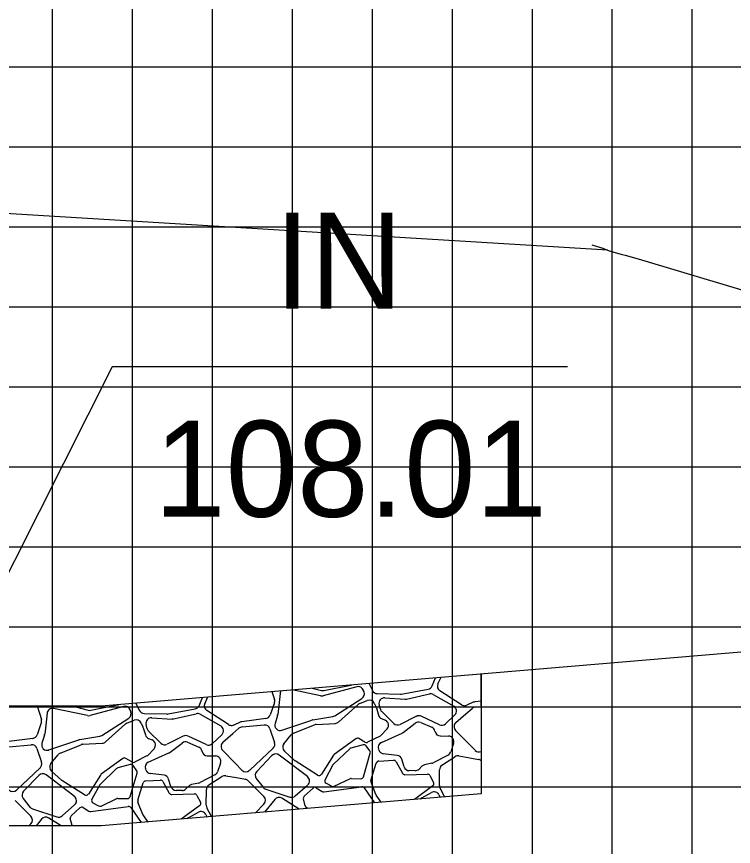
# Model space of a CAD drawing. Extents: x 1685192 to 1685536, y 461260 to 461480.
# Drawn here: x 1685380.78 to 1685389.74, y 461431.46 to 461441.84 of the extents above; entities that cross this region are included whole.
import ezdxf

# ---------------------------------------------------------------- set-up
doc = ezdxf.new("R2010")
doc.units = 0
for name, color, linetype in [('ANNOTATION', 7, 'Continuous'), ('D_Roadway_Centerline', 7, 'Continuous'), ('D_Roadway_SlopeLines', 7, 'Continuous'), ('MAJOR', 7, 'Continuous'), ('MINOR', 7, 'Continuous'), ('S_Roadway_Centerline', 7, 'Continuous')]:
    doc.layers.add(name, color=color, linetype=linetype)

msp = doc.modelspace()

# ---------------------------------------------------------------- linework, layer by layer
at = {"layer": 'ANNOTATION'}
msp.add_lwpolyline([(1685387.668, 461437.456), (1685381.977, 461437.456), (1685379.839, 461433.216)], dxfattribs=at)
at = {"layer": 'D_Roadway_Centerline'}
for p, q in [((1685385.186, 461433.5), (1685385.229, 461433.41)), ((1685385.977, 461433.468), (1685386.019, 461433.57)), ((1685386.049, 461433.492), (1685386.088, 461433.576)), ((1685383.974, 461433.397), (1685384.005, 461433.296)), ((1685384.582, 461433.343), (1685384.226, 461433.418)), ((1685384.477, 461433.439), (1685384.592, 461433.41)), ((1685385.035, 461433.457), (1685384.614, 461433.344)), ((1685384.622, 461433.41), (1685384.958, 461433.477)), ((1685385.125, 461433.392), (1685385.116, 461433.415)), ((1685385.589, 461433.364), (1685385.926, 461433.426)), ((1685386.345, 461433.23), (1685386.073, 461433.406)), ((1685383.063, 461433.22), (1685383.104, 461433.323)), ((1685383.134, 461433.245), (1685383.174, 461433.329)), ((1685384.076, 461433.373), (1685384.046, 461433.11)), ((1685384.76, 461433.095), (1685385.097, 461433.311)), ((1685385.072, 461433.247), (1685385.165, 461433.285)), ((1685385.289, 461433.371), (1685385.575, 461433.363)), ((1685385.385, 461433.317), (1685385.638, 461433.301)), ((1685385.657, 461433.302), (1685385.942, 461433.367)), ((1685385.991, 461433.36), (1685386.247, 461433.214)), ((1685386.589, 461433.278), (1685386.51, 461433.268)), ((1685381.039, 461433.216), (1685381.091, 461433.049)), ((1685381.668, 461433.096), (1685381.244, 461433.185)), ((1685381.47, 461433.216), (1685381.677, 461433.163)), ((1685382.12, 461433.21), (1685381.699, 461433.097)), ((1685381.708, 461433.162), (1685382.043, 461433.23)), ((1685382.272, 461433.252), (1685382.315, 461433.162)), ((1685382.675, 461433.117), (1685383.012, 461433.179)), ((1685384.004, 461433.254), (1685383.953, 461433.104)), ((1685384.808, 461433.016), (1685385.052, 461433.235)), ((1685385.253, 461433.25), (1685385.275, 461433.201)), ((1685385.279, 461433.192), (1685385.305, 461433.102)), ((1685385.329, 461433.178), (1685385.314, 461433.231)), ((1685386.399, 461433.119), (1685386.475, 461433.185)), ((1685386.491, 461433.262), (1685386.41, 461433.226)), ((1685386.514, 461433.202), (1685386.589, 461433.208)), ((1685381.162, 461433.126), (1685381.132, 461432.863)), ((1685382.21, 461433.145), (1685382.202, 461433.167)), ((1685382.375, 461433.124), (1685382.66, 461433.116)), ((1685382.471, 461433.069), (1685382.724, 461433.053)), ((1685382.743, 461433.055), (1685383.028, 461433.12)), ((1685383.077, 461433.112), (1685383.333, 461432.966)), ((1685383.431, 461432.983), (1685383.159, 461433.158)), ((1685384.043, 461433.097), (1685384.012, 461432.999)), ((1685384.484, 461433.043), (1685384.734, 461433.085)), ((1685385.498, 461432.998), (1685385.347, 461433.147)), ((1685385.779, 461433.087), (1685385.576, 461432.986)), ((1685386.067, 461432.98), (1685385.839, 461433.087)), ((1685386.26, 461433.105), (1685386.143, 461432.993)), ((1685386.274, 461433.01), (1685386.399, 461433.119)), ((1685381.09, 461433.006), (1685381.038, 461432.857)), ((1685381.846, 461432.847), (1685382.183, 461433.064)), ((1685381.893, 461432.768), (1685382.138, 461432.987)), ((1685382.158, 461433), (1685382.251, 461433.038)), ((1685382.339, 461433.003), (1685382.361, 461432.954)), ((1685382.415, 461432.93), (1685382.4, 461432.983)), ((1685383.577, 461433.015), (1685383.496, 461432.978)), ((1685383.897, 461433.059), (1685383.596, 461433.02)), ((1685383.6, 461432.955), (1685383.878, 461432.979)), ((1685384.099, 461432.913), (1685384.474, 461433.04)), ((1685384.241, 461432.875), (1685384.504, 461432.98)), ((1685384.525, 461432.985), (1685384.766, 461432.998)), ((1685385.345, 461433.058), (1685385.39, 461433.039)), ((1685385.614, 461432.884), (1685385.765, 461433)), ((1685385.833, 461433.009), (1685385.972, 461432.95)), ((1685382.365, 461432.945), (1685382.391, 461432.855)), ((1685382.583, 461432.751), (1685382.433, 461432.899)), ((1685383.36, 461432.763), (1685383.485, 461432.872)), ((1685383.485, 461432.872), (1685383.561, 461432.938)), ((1685383.949, 461432.932), (1685384.007, 461432.759)), ((1685385.413, 461432.93), (1685385.335, 461432.846)), ((1685385.342, 461432.76), (1685385.6, 461432.876)), ((1685386.012, 461432.901), (1685386.013, 461432.896)), ((1685386.431, 461432.746), (1685386.27, 461432.911)), ((1685380.982, 461432.811), (1685380.682, 461432.773)), ((1685381.129, 461432.85), (1685381.098, 461432.751)), ((1685381.185, 461432.666), (1685381.56, 461432.793)), ((1685381.57, 461432.795), (1685381.82, 461432.838)), ((1685382.43, 461432.811), (1685382.475, 461432.792)), ((1685382.865, 461432.839), (1685382.662, 461432.738)), ((1685382.919, 461432.762), (1685383.058, 461432.703)), ((1685383.152, 461432.733), (1685382.925, 461432.84)), ((1685383.346, 461432.857), (1685383.229, 461432.745)), ((1685384.124, 461432.743), (1685384.213, 461432.854)), ((1685385.022, 461432.807), (1685384.753, 461432.609)), ((1685385.136, 461432.763), (1685385.06, 461432.808)), ((1685385.325, 461432.838), (1685385.169, 461432.762)), ((1685386.079, 461432.842), (1685386.181, 461432.84)), ((1685380.686, 461432.707), (1685380.964, 461432.731)), ((1685381.035, 461432.685), (1685381.092, 461432.512)), ((1685381.327, 461432.628), (1685381.59, 461432.732)), ((1685381.611, 461432.737), (1685381.852, 461432.751)), ((1685382.499, 461432.682), (1685382.42, 461432.598)), ((1685382.7, 461432.637), (1685382.851, 461432.753)), ((1685383.517, 461432.499), (1685383.356, 461432.663)), ((1685383.988, 461432.688), (1685383.695, 461432.412)), ((1685384.947, 461432.681), (1685384.743, 461432.487)), ((1685385.115, 461432.731), (1685384.961, 461432.69)), ((1685385.197, 461432.654), (1685385.152, 461432.718)), ((1685385.309, 461432.666), (1685385.305, 461432.676)), ((1685386.245, 461432.749), (1685386.208, 461432.641)), ((1685386.514, 461432.662), (1685386.431, 461432.746)), ((1685381.21, 461432.496), (1685381.299, 461432.607)), ((1685382.108, 461432.559), (1685381.838, 461432.362)), ((1685382.222, 461432.516), (1685382.145, 461432.561)), ((1685382.41, 461432.591), (1685382.254, 461432.514)), ((1685382.428, 461432.513), (1685382.686, 461432.629)), ((1685383.098, 461432.654), (1685383.099, 461432.649)), ((1685383.164, 461432.594), (1685383.267, 461432.592)), ((1685383.973, 461432.595), (1685383.783, 461432.398)), ((1685384.416, 461432.334), (1685384.064, 461432.602)), ((1685384.257, 461432.535), (1685384.131, 461432.65)), ((1685384.744, 461432.6), (1685384.592, 461432.362)), ((1685385.118, 461432.331), (1685385.202, 461432.625)), ((1685385.539, 461432.598), (1685385.366, 461432.619)), ((1685385.625, 461432.456), (1685385.596, 461432.551)), ((1685386.175, 461432.602), (1685385.989, 461432.506)), ((1685386.099, 461432.476), (1685386.262, 461432.581)), ((1685386.311, 461432.591), (1685386.446, 461432.567)), ((1685386.446, 461432.567), (1685386.555, 461432.548)), ((1685382.201, 461432.484), (1685382.047, 461432.442)), ((1685382.283, 461432.407), (1685382.238, 461432.471)), ((1685383.331, 461432.502), (1685383.294, 461432.394)), ((1685383.599, 461432.414), (1685383.517, 461432.499)), ((1685384.545, 461432.351), (1685384.262, 461432.532)), ((1685384.736, 461432.479), (1685384.637, 461432.299)), ((1685385.211, 461432.285), (1685385.278, 461432.503)), ((1685385.309, 461432.527), (1685385.494, 461432.537)), ((1685385.526, 461432.519), (1685385.604, 461432.375)), ((1685385.848, 461432.462), (1685385.813, 461432.427)), ((1685385.972, 461432.5), (1685385.882, 461432.481)), ((1685381.074, 461432.441), (1685380.781, 461432.165)), ((1685381.059, 461432.348), (1685380.869, 461432.151)), ((1685381.502, 461432.087), (1685381.15, 461432.355)), ((1685381.343, 461432.288), (1685381.217, 461432.403)), ((1685381.83, 461432.353), (1685381.678, 461432.114)), ((1685382.032, 461432.434), (1685381.828, 461432.24)), ((1685382.203, 461432.084), (1685382.288, 461432.378)), ((1685382.395, 461432.418), (1685382.391, 461432.429)), ((1685382.624, 461432.351), (1685382.451, 461432.371)), ((1685383.26, 461432.355), (1685383.075, 461432.259)), ((1685383.396, 461432.344), (1685383.532, 461432.32)), ((1685385.635, 461432.357), (1685385.918, 461432.365)), ((1685385.763, 461432.406), (1685385.69, 461432.408)), ((1685385.949, 461432.346), (1685385.994, 461432.261)), ((1685386.067, 461432.222), (1685386.068, 461432.419)), ((1685381.63, 461432.104), (1685381.348, 461432.284)), ((1685382.297, 461432.037), (1685382.364, 461432.256)), ((1685382.395, 461432.28), (1685382.58, 461432.29)), ((1685382.611, 461432.272), (1685382.69, 461432.128)), ((1685382.711, 461432.208), (1685382.682, 461432.303)), ((1685383.058, 461432.252), (1685382.968, 461432.233)), ((1685383.185, 461432.229), (1685383.347, 461432.334)), ((1685383.532, 461432.32), (1685383.641, 461432.301)), ((1685383.678, 461432.282), (1685383.872, 461432.086)), ((1685383.778, 461432.309), (1685383.863, 461432.2)), ((1685384.65, 461432.252), (1685384.721, 461432.213)), ((1685384.752, 461432.212), (1685384.947, 461432.305)), ((1685384.963, 461432.308), (1685385.084, 461432.307)), ((1685385.274, 461432.108), (1685385.212, 461432.262)), ((1685381.822, 461432.232), (1685381.723, 461432.051)), ((1685382.849, 461432.159), (1685382.776, 461432.16)), ((1685382.933, 461432.215), (1685382.898, 461432.179)), ((1685383.153, 461431.975), (1685383.154, 461432.172)), ((1685383.895, 461432.177), (1685384.199, 461432.078)), ((1685384.265, 461432.091), (1685384.42, 461432.228)), ((1685384.377, 461432.09), (1685384.487, 461432.19)), ((1685384.528, 461432.194), (1685384.6, 461432.148)), ((1685384.623, 461432.142), (1685385.092, 461432.207)), ((1685385.125, 461432.193), (1685385.254, 461432.005)), ((1685385.984, 461432.217), (1685385.754, 461432.048)), ((1685385.847, 461432.069), (1685385.968, 461432.135)), ((1685386.132, 461432.08), (1685386.075, 461432.191)), ((1685380.764, 461432.035), (1685380.958, 461431.839)), ((1685380.864, 461432.061), (1685380.948, 461431.953)), ((1685381.838, 461431.965), (1685382.033, 461432.058)), ((1685382.048, 461432.061), (1685382.17, 461432.059)), ((1685382.721, 461432.11), (1685383.004, 461432.118)), ((1685383.035, 461432.099), (1685383.08, 461432.013)), ((1685384.008, 461432.047), (1685383.881, 461431.889)), ((1685384.312, 461431.925), (1685384.098, 461432.062)), ((1685384.388, 461431.969), (1685384.367, 461432.056)), ((1685385.34, 461432.013), (1685385.278, 461432.101)), ((1685385.828, 461432.054), (1685385.834, 461432.06)), ((1685386.061, 461432.107), (1685386.078, 461432.075)), ((1685380.981, 461431.93), (1685381.284, 461431.83)), ((1685381.351, 461431.844), (1685381.506, 461431.981)), ((1685381.463, 461431.842), (1685381.573, 461431.943)), ((1685381.614, 461431.946), (1685381.686, 461431.9)), ((1685381.709, 461431.895), (1685382.178, 461431.96)), ((1685381.736, 461432.005), (1685381.807, 461431.966)), ((1685382.211, 461431.945), (1685382.34, 461431.758)), ((1685382.36, 461431.861), (1685382.298, 461432.015)), ((1685383.07, 461431.97), (1685382.84, 461431.8)), ((1685383.218, 461431.833), (1685383.16, 461431.943)), ((1685383.873, 461431.99), (1685383.766, 461431.879)), ((1685384.424, 461431.935), (1685384.403, 461431.948)), ((1685382.426, 461431.765), (1685382.363, 461431.854)), ((1685382.933, 461431.821), (1685383.054, 461431.888)), ((1685383.147, 461431.86), (1685383.164, 461431.828)), ((1685380.959, 461431.743), (1685380.933, 461431.716)), ((1685381.094, 461431.799), (1685381.026, 461431.716)), ((1685381.339, 461431.716), (1685381.184, 461431.814)), ((1685381.474, 461431.722), (1685381.452, 461431.809)), ((1685382.914, 461431.807), (1685382.92, 461431.812))]:
    msp.add_line(p, q, dxfattribs=at)
for points in [[(1685386.589, 461433.216), (1685386.589, 461433.619), (1685386.589, 461432.119), (1685381.839, 461431.716)], [(1685379.839, 461433.216), (1685381.839, 461433.216)], [(1685381.839, 461431.716), (1685379.812, 461431.716)]]:
    msp.add_lwpolyline(points, dxfattribs=at)
for centre, radius, start, end in [((1685386.11, 461433.463), 0.0684, 154.6779, 237.1572), ((1685384.144, 461433.366), 0.0684, 143.199, 173.5581), ((1685384.609, 461433.477), 0.0684, 255.7876, 281.376), ((1685384.944, 461433.544), 0.0684, 281.376, 293.4538), ((1685385.052, 461433.391), 0.0684, 20.3756, 105.0057), ((1685385.061, 461433.369), 0.0684, 302.6529, 20.3756), ((1685385.291, 461433.439), 0.0684, 205.776, 268.3684), ((1685385.914, 461433.494), 0.0684, 280.4508, 337.8206), ((1685383.94, 461433.276), 0.0684, 340.889, 17.2589), ((1685384.596, 461433.41), 0.0684, 258.1184, 285.0057), ((1685385.191, 461433.222), 0.0684, 24.3881, 112.133), ((1685385.38, 461433.249), 0.0684, 86.3803, 195.1563), ((1685385.577, 461433.431), 0.0684, 268.3684, 280.4508), ((1685385.642, 461433.369), 0.0684, 266.3803, 282.7949), ((1685385.957, 461433.3), 0.0684, 60.2889, 102.7949), ((1685381.23, 461433.118), 0.0684, 78.1184, 173.5581), ((1685382.03, 461433.297), 0.0684, 281.376, 293.4538), ((1685382.138, 461433.144), 0.0684, 20.3756, 105.0057), ((1685382.999, 461433.246), 0.0684, 280.4508, 337.8206), ((1685383.196, 461433.216), 0.0684, 154.6779, 237.1572), ((1685385.098, 461433.184), 0.0684, 112.133, 131.8402), ((1685385.213, 461433.173), 0.0684, 16.4851, 24.3881), ((1685385.395, 461433.195), 0.0684, 195.1563, 225.4528), ((1685386.213, 461433.154), 0.0684, 313.736, 60.2889), ((1685386.382, 461433.288), 0.0684, 237.1572, 277.5302), ((1685386.382, 461433.288), 0.0684, 277.5302, 294.2915), ((1685386.52, 461433.134), 0.0684, 94.9402, 131.0707), ((1685386.519, 461433.2), 0.0684, 97.2881, 114.2915), ((1685381.682, 461433.163), 0.0684, 258.1184, 285.0057), ((1685381.694, 461433.229), 0.0684, 255.7876, 281.376), ((1685382.146, 461433.121), 0.0684, 302.6529, 20.3756), ((1685382.377, 461433.192), 0.0684, 205.776, 268.3684), ((1685382.466, 461433.001), 0.0684, 86.3803, 195.1563), ((1685382.662, 461433.184), 0.0684, 268.3684, 280.4508), ((1685383.043, 461433.053), 0.0684, 60.2889, 102.7949), ((1685383.888, 461433.127), 0.0684, 277.2881, 340.889), ((1685383.978, 461433.118), 0.0684, 342.329, 353.5581), ((1685384.723, 461433.152), 0.0684, 279.6151, 302.6529), ((1685385.371, 461433.121), 0.0684, 196.4851, 247.2055), ((1685385.81, 461433.025), 0.0684, 64.7829, 116.3924), ((1685381.026, 461433.029), 0.0684, 340.889, 17.2589), ((1685382.184, 461432.937), 0.0684, 112.133, 131.8402), ((1685382.277, 461432.974), 0.0684, 24.3881, 112.133), ((1685382.728, 461433.122), 0.0684, 266.3803, 282.7949), ((1685383.299, 461432.907), 0.0684, 313.736, 60.2889), ((1685383.468, 461433.041), 0.0684, 237.1572, 277.5302), ((1685383.468, 461433.041), 0.0684, 277.5302, 294.2915), ((1685383.605, 461432.952), 0.0684, 97.2881, 114.2915), ((1685383.884, 461432.91), 0.0684, 18.4334, 94.9402), ((1685384.077, 461432.978), 0.0684, 162.329, 288.7109), ((1685384.496, 461432.975), 0.0684, 99.6151, 108.7109), ((1685384.529, 461432.916), 0.0684, 93.2821, 111.7501), ((1685384.762, 461433.067), 0.0684, 273.2821, 311.8402), ((1685385.363, 461432.976), 0.0684, 317.0588, 67.2055), ((1685385.546, 461433.047), 0.0684, 225.4528, 296.3924), ((1685385.806, 461432.946), 0.0684, 67.0039, 127.532), ((1685386.096, 461433.042), 0.0684, 244.7829, 313.736), ((1685386.319, 461432.959), 0.0684, 131.0707, 224.3226), ((1685381.064, 461432.87), 0.0684, 342.329, 353.5581), ((1685382.299, 461432.925), 0.0684, 16.4851, 24.3881), ((1685382.481, 461432.948), 0.0684, 195.1563, 225.4528), ((1685383.606, 461432.886), 0.0684, 94.9402, 131.0707), ((1685384.267, 461432.811), 0.0684, 111.7501, 141.2154), ((1685385.572, 461432.939), 0.0684, 294.2574, 307.532), ((1685385.945, 461432.887), 0.0684, 11.6942, 67.0039), ((1685386.08, 461432.91), 0.0684, 191.6942, 268.7973), ((1685380.974, 461432.879), 0.0684, 277.2881, 340.889), ((1685381.582, 461432.728), 0.0684, 99.6151, 108.7109), ((1685381.809, 461432.905), 0.0684, 279.6151, 302.6529), ((1685381.848, 461432.819), 0.0684, 273.2821, 311.8402), ((1685382.457, 461432.874), 0.0684, 196.4851, 247.2055), ((1685382.449, 461432.729), 0.0684, 317.0588, 67.2055), ((1685382.892, 461432.699), 0.0684, 67.0039, 127.532), ((1685382.895, 461432.778), 0.0684, 64.7829, 116.3924), ((1685383.405, 461432.711), 0.0684, 131.0707, 224.3226), ((1685383.942, 461432.738), 0.0684, 313.2245, 18.4334), ((1685385.042, 461432.779), 0.0342, 59.3138, 126.2245), ((1685385.154, 461432.792), 0.0342, 239.3138, 296.0455), ((1685385.37, 461432.698), 0.0684, 114.2574, 197.9855), ((1685385.31, 461432.869), 0.0342, 296.0455, 317.0588), ((1685386.18, 461432.771), 0.0684, 341.1694, 88.7973), ((1685380.97, 461432.663), 0.0684, 18.4334, 94.9402), ((1685381.163, 461432.73), 0.0684, 162.329, 288.7109), ((1685381.615, 461432.669), 0.0684, 93.2821, 111.7501), ((1685382.631, 461432.8), 0.0684, 225.4528, 296.3924), ((1685383.031, 461432.64), 0.0684, 11.6942, 67.0039), ((1685383.181, 461432.795), 0.0684, 244.7829, 313.736), ((1685384.177, 461432.701), 0.0684, 141.2154, 227.6405), ((1685384.97, 461432.657), 0.0342, 105.0554, 133.6256), ((1685385.124, 461432.698), 0.0342, 35.5021, 105.0554), ((1685385.17, 461432.634), 0.0342, 343.8586, 35.5021), ((1685385.374, 461432.687), 0.0684, 197.9855, 263.2178), ((1685386.563, 461432.709), 0.0684, 224.3226, 292.7378), ((1685381.352, 461432.564), 0.0684, 111.7501, 141.2154), ((1685382.128, 461432.532), 0.0342, 59.3138, 126.2245), ((1685382.395, 461432.621), 0.0342, 296.0455, 317.0588), ((1685382.658, 461432.691), 0.0684, 294.2574, 307.532), ((1685383.166, 461432.663), 0.0684, 191.6942, 268.7973), ((1685383.266, 461432.524), 0.0684, 341.1694, 88.7973), ((1685384.022, 461432.548), 0.0684, 52.729, 136.0977), ((1685384.773, 461432.582), 0.0342, 126.2245, 147.4461), ((1685385.531, 461432.53), 0.0684, 17.2589, 83.2178), ((1685386.143, 461432.663), 0.0684, 297.4713, 341.1694), ((1685386.299, 461432.524), 0.0684, 80.1079, 122.9239), ((1685381.027, 461432.49), 0.0684, 313.2245, 18.4334), ((1685381.263, 461432.453), 0.0684, 141.2154, 227.6405), ((1685382.21, 461432.451), 0.0342, 35.5021, 105.0554), ((1685382.239, 461432.545), 0.0342, 239.3138, 296.0455), ((1685382.456, 461432.45), 0.0684, 114.2574, 197.9855), ((1685384.28, 461432.561), 0.0342, 227.6405, 237.4461), ((1685384.766, 461432.462), 0.0342, 133.6256, 151.1614), ((1685385.311, 461432.493), 0.0342, 92.9736, 163.05), ((1685385.496, 461432.503), 0.0342, 28.601, 92.9736), ((1685385.691, 461432.476), 0.0684, 197.2589, 269.1409), ((1685385.896, 461432.414), 0.0684, 101.9765, 135.216), ((1685385.958, 461432.567), 0.0684, 281.9765, 297.4713), ((1685386.137, 461432.419), 0.0684, 122.9239, 179.657), ((1685386.543, 461432.481), 0.0684, 48.1626, 80.1079), ((1685381.108, 461432.301), 0.0684, 52.729, 136.0977), ((1685381.859, 461432.334), 0.0342, 126.2245, 147.4461), ((1685382.056, 461432.409), 0.0342, 105.0554, 133.6256), ((1685382.255, 461432.387), 0.0342, 343.8586, 35.5021), ((1685382.46, 461432.439), 0.0684, 197.9855, 263.2178), ((1685382.616, 461432.283), 0.0684, 17.2589, 83.2178), ((1685383.229, 461432.416), 0.0684, 297.4713, 341.1694), ((1685383.385, 461432.276), 0.0684, 80.1079, 122.9239), ((1685383.648, 461432.462), 0.0684, 224.3226, 313.2245), ((1685383.832, 461432.351), 0.0684, 136.0977, 217.814), ((1685384.563, 461432.38), 0.0342, 237.4461, 327.4461), ((1685385.634, 461432.392), 0.0342, 208.601, 271.5241), ((1685385.764, 461432.475), 0.0684, 269.1409, 315.216), ((1685385.919, 461432.331), 0.0342, 27.4713, 91.5241), ((1685381.366, 461432.313), 0.0342, 227.6405, 237.4461), ((1685381.852, 461432.215), 0.0342, 133.6256, 151.1614), ((1685382.397, 461432.246), 0.0342, 92.9736, 163.05), ((1685382.581, 461432.255), 0.0342, 28.601, 92.9736), ((1685383.044, 461432.319), 0.0684, 281.9765, 297.4713), ((1685383.629, 461432.234), 0.0684, 44.809, 80.1079), ((1685384.375, 461432.28), 0.0684, 311.4585, 52.729), ((1685384.667, 461432.282), 0.0342, 151.1614, 241.1614), ((1685384.962, 461432.274), 0.0342, 89.2793, 115.3349), ((1685385.085, 461432.341), 0.0342, 269.2793, 343.8586), ((1685385.244, 461432.275), 0.0342, 163.05, 201.779), ((1685385.964, 461432.245), 0.0342, 306.4028, 27.4713), ((1685380.734, 461432.215), 0.0684, 224.3226, 313.2245), ((1685380.918, 461432.103), 0.0684, 136.0977, 217.814), ((1685382.777, 461432.229), 0.0684, 197.2589, 269.1409), ((1685382.85, 461432.227), 0.0684, 269.1409, 315.216), ((1685382.982, 461432.166), 0.0684, 101.9765, 135.216), ((1685383.222, 461432.171), 0.0684, 122.9239, 179.657), ((1685383.917, 461432.242), 0.0684, 217.814, 251.8293), ((1685384.51, 461432.165), 0.0342, 57.2829, 132.3863), ((1685384.618, 461432.176), 0.0342, 237.2829, 277.8418), ((1685384.737, 461432.243), 0.0342, 241.1614, 295.3349), ((1685385.097, 461432.173), 0.0342, 34.6434, 97.8418), ((1685386.001, 461432.075), 0.0684, 28.2367, 118.7116), ((1685386.135, 461432.222), 0.0684, 179.657, 207.3309), ((1685381.461, 461432.032), 0.0684, 311.4585, 52.729), ((1685381.649, 461432.133), 0.0342, 237.4461, 327.4461), ((1685381.753, 461432.035), 0.0342, 151.1614, 241.1614), ((1685382.048, 461432.027), 0.0342, 89.2793, 115.3349), ((1685382.17, 461432.094), 0.0342, 269.2793, 343.8586), ((1685382.33, 461432.027), 0.0342, 163.05, 201.779), ((1685382.72, 461432.144), 0.0342, 208.601, 271.5241), ((1685383.005, 461432.083), 0.0342, 27.4713, 91.5241), ((1685383.824, 461432.038), 0.0684, 316.1085, 44.809), ((1685384.061, 461432.004), 0.0684, 57.4882, 141.2836), ((1685384.22, 461432.143), 0.0684, 251.8293, 311.4585), ((1685384.4, 461432.064), 0.0342, 132.3863, 193.5976), ((1685385.306, 461432.121), 0.0342, 201.779, 215.3617), ((1685385.88, 461432.009), 0.0684, 118.7116, 131.8713), ((1685381.002, 461431.995), 0.0684, 217.814, 251.8293), ((1685381.596, 461431.917), 0.0342, 57.2829, 132.3863), ((1685381.823, 461431.996), 0.0342, 241.1614, 295.3349), ((1685382.182, 461431.926), 0.0342, 34.6434, 97.8418), ((1685383.05, 461431.998), 0.0342, 306.4028, 27.4713), ((1685383.221, 461431.975), 0.0684, 179.657, 207.3309), ((1685384.421, 461431.977), 0.0342, 193.5976, 238.5378), ((1685380.91, 461431.79), 0.0684, 316.1085, 44.809), ((1685381.147, 461431.757), 0.0684, 57.4882, 141.2836), ((1685381.306, 461431.895), 0.0684, 251.8293, 311.4585), ((1685381.486, 461431.817), 0.0342, 132.3863, 193.5976), ((1685381.704, 461431.929), 0.0342, 237.2829, 277.8418), ((1685382.391, 461431.873), 0.0342, 201.779, 215.3617), ((1685383.087, 461431.828), 0.0684, 28.2367, 118.7116), ((1685381.507, 461431.73), 0.0342, 193.5976, 204.5152), ((1685382.965, 461431.761), 0.0684, 118.7116, 131.8713)]:
    msp.add_arc(centre, radius, start, end, dxfattribs=at)
at = {"layer": 'D_Roadway_SlopeLines'}
msp.add_line((1685381.839, 461433.216), (1685402.509, 461434.97), dxfattribs=at)
at = {"layer": 'MAJOR'}
for p, q in [((1685388.229, 461425.206), (1685388.229, 461450.206)), ((1685218.229, 461440.206), (1685498.229, 461440.206)), ((1685218.229, 461435.206), (1685498.229, 461435.206))]:
    msp.add_line(p, q, dxfattribs=at)
at = {"layer": 'MINOR'}
for p, q in [((1685381.229, 461425.206), (1685381.229, 461450.206)), ((1685382.229, 461425.206), (1685382.229, 461450.206)), ((1685383.229, 461425.206), (1685383.229, 461450.206)), ((1685384.229, 461425.206), (1685384.229, 461450.206)), ((1685385.229, 461425.206), (1685385.229, 461450.206)), ((1685386.229, 461425.206), (1685386.229, 461450.206)), ((1685387.229, 461425.206), (1685387.229, 461450.206)), ((1685389.229, 461425.206), (1685389.229, 461450.206)), ((1685218.229, 461441.206), (1685498.229, 461441.206)), ((1685218.229, 461439.206), (1685498.229, 461439.206)), ((1685218.229, 461438.206), (1685498.229, 461438.206)), ((1685218.229, 461437.206), (1685498.229, 461437.206)), ((1685218.229, 461436.206), (1685498.229, 461436.206)), ((1685218.229, 461434.206), (1685498.229, 461434.206)), ((1685218.229, 461433.206), (1685498.229, 461433.206)), ((1685218.229, 461432.206), (1685498.229, 461432.206))]:
    msp.add_line(p, q, dxfattribs=at)
at = {"layer": 'S_Roadway_Centerline'}
for points in [[(1685286.43, 461435.332), (1685288.431, 461435.437), (1685289.361, 461435.639), (1685289.912, 461435.758), (1685306.542, 461439.532), (1685306.637, 461439.548), (1685308.936, 461439.765), (1685313.647, 461440.214), (1685314.316, 461440.255), (1685330.697, 461440.593), (1685332.454, 461440.571), (1685336.875, 461440.432), (1685338.988, 461440.38), (1685348.379, 461439.9), (1685358.138, 461440.263), (1685360.692, 461440.305), (1685367.617, 461440.119), (1685369.76, 461440.052), (1685370.232, 461439.98), (1685380.088, 461439.409), (1685388.173, 461438.92)], [(1685387.972, 461438.982), (1685388.109, 461438.941), (1685388.189, 461438.907), (1685388.354, 461438.861), (1685388.388, 461438.852), (1685388.55, 461438.807), (1685392.101, 461437.742), (1685395.366, 461436.873), (1685396.058, 461436.688), (1685398.256, 461436.103), (1685399.527, 461435.764), (1685402.509, 461434.97), (1685402.699, 461435.069), (1685402.802, 461435.111), (1685404.747, 461435.903), (1685405.282, 461436.177)]]:
    msp.add_lwpolyline(points, dxfattribs=at)

# ---------------------------------------------------------------- texts
at = {"layer": 'ANNOTATION'}
for s, p in [('IN', (1685384.004, 461438.182)), ('108.01', (1685382.503, 461435.582))]:
    msp.add_text(s, height=1.2, dxfattribs=at).set_placement(p)

doc.saveas('drawing.dxf')
